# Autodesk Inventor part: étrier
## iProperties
Shininess: 64.0
Length Units: 11269
Angle Units: 11279
Time Units: 11290
Mass Units: 11283
Length Display Precision: 3
Angle Display Precision: 2
Compacted: True
Part Number: étrier
Document SubType Name: Modeling
Created: 2005-01
Material: Par défaut
Designer: LEGERET Philippe
Density: 0.0
Volumn: 0.0
Area: 0.0
PropertySet Name: Model Information
Control State: 0
Master: False
Checked Out: False
Author: LEGERET Philippe
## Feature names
1. Extrusion1
2. Perçage1 [Hole]
